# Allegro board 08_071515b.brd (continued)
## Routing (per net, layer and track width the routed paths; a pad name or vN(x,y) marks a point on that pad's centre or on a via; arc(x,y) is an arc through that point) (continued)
UNNAMED_14_ADLT8636_I23_TR: length 2.3
  TOP w0.254: VR1.18 17.78,12.64 17.21,12.07 C204.1
UNNAMED_14_ADLTC3307_I51_FB: length 3.6
  TOP w0.254: R108.2 C220.2 ; C220.2 U17.12 ; C220.2 R109.1
UNNAMED_14_ADLTC3307_I51_MODE: length 1.8
  TOP w0.14: v1(43.56,14.61) 43.63,14.67 U17.9
  BOTTOM w0.508: R5.2 42.97,14.61 v1(43.56,14.61)
UNNAMED_14_ADLTC3310_I15_FB: length 10.5
  TOP w0.254: U16.18 C208.2
  TOP w0.305: 33.66,13.58 33.66,11.66 34.14,11.17 R97.2 R107.1 C209.1 ; 33.66,13.58 34.54,13.58 R101.2 35.81,13.71 R102.1 ; 33.66,13.58 C208.2
UNNAMED_14_ADLTC3310_I15_ITH: length 9.5
  TOP w0.254: U16.17 32.38,14.28 31.68,13.58
  TOP w0.305: C193.1 C195.1 31.68,13.58 31.94,13.32 31.94,10.73 32.5,10.17 R97.1
UNNAMED_14_ADLTC3310_I15_PGOOD: length 2.2
  TOP w0.254: U16.14 30.73,15.64 30.1,15.64 29.46,14.99 R99.1
UNNAMED_14_ADLTC3310_I15_SSTT: length 3.9
  TOP w0.254: C202.1 29.08,13.65 29.72,14.29 31.44,14.29 31.88,14.73 U16.16
UNNAMED_14_CAP_I9_N2: length 2.8
  TOP w0.305: R91.1 30.87,10.61 31.11,10.86 C195.2
UNNAMED_14_RES_I39_N1: length 1.7
  TOP w0.305: R103.1 37.27,12.71 36.07,12.71 R102.2
UNNAMED_17_ADSP21835_I205_DMC0VREF1: length 27.5
  TOP w0.14: 41.25,56.54 41.02,56.54 U1.G20
  TOP w0.203: U1.J4 v1(27.42,54.94)
  TOP w0.305: v1(43.02,56.54) 41.25,56.54
  L7_SIG w0.127: 34.54,53.34 34.16,52.95 31.25,52.95 30.8,53.4 31.12,53.73 34.16,53.73 34.54,53.34
  L7_SIG w0.406: v1(27.42,54.94) 27.42,54.11 28.13,53.4 30.8,53.4 ; v1(43.02,56.54) 43.02,54.45 41.91,53.34 34.54,53.34
  BOTTOM w0.406: R2.2 v1(43.02,56.54)
UNNAMED_17_CAP_I61_N1: length 7.5
  TOP w0.14: U8.M8 v1(35.42,79.14)
  TOP w0.203: U8.H1 32.22,72.74
  TOP w0.406: 36.22,81.74 v1(36.22,80.74) ; 32.22,72.74 C32.1
  L4_SIG w0.406: v1(35.42,79.14) 35.03,79.14 34.75,79.43 34.75,80.43 35.05,80.74 v1(36.22,80.74)
UNNAMED_17_ICIS4XTR16256_I45_ZQ: length 3.3
  TOP w0.203: U8.L8 34.62,79.14 R4.1
UNNAMED_18_ICIS25XP512M_I1_SCK: length 4.6
  TOP w0.14: U4.B2 16.14,32.5 17.76,32.5 17.91,32.64 R49.2 R50.1
UNNAMED_18_ICIS25XP512M_I1_SO: length 4.9
  TOP w0.14: R51.2 R52.1 18.29,35.18 17.53,34.42 16.22,34.42 U4.D2
USB_DM: length 28.6
  TOP w0.133: D1.3 15.36,91.06 15.48,90.94 15.48,90.16 v1(15.18,89.86) 15.48,89.55 15.48,89.39 15.37,89.28 U15.5 ; P1.A7 30.24,91.02 30.33,90.93 30.33,90.11 v1(30.06,89.84)
  BOTTOM w0.133: v1(15.18,89.86) 15.48,89.55 15.48,89.1 15.76,88.82 17.17,88.82 18.84,90.49 30.18,90.49 30.36,90.31 30.36,90.14 v1(30.06,89.84) 30.36,89.54 30.36,89.25 30.64,88.96 31.6,88.96 31.88,89.25 31.88,90.97 31.6,91.25 30.74,91.25 30.61,91.39 30.61,91.58 30.88,91.85 P1.B7
USB_DP: length 27.8
  TOP w0.133: D1.4 15.87,91.06 15.74,90.93 15.74,90.16 v1(16.04,89.86) 15.74,89.55 15.74,89.42 15.87,89.28 U15.4 ; P1.A6 30.63,90.92 30.63,90.13 v1(30.92,89.84)
  BOTTOM w0.133: v1(16.04,89.86) 15.74,89.55 15.74,89.21 15.87,89.07 17.06,89.07 18.73,90.74 30.29,90.74 30.62,90.42 30.62,90.14 v1(30.92,89.84) 30.62,89.54 30.62,89.35 30.75,89.22 31.49,89.22 31.62,89.35 31.62,90.87 31.49,91 30.63,91 30.35,91.28 30.35,91.58 30.08,91.85 P1.B6
USB_TYPEC: length 12.3
  TOP w0.305: C158.1 29.23,89.77 P1.A9 29.23,92.22 P1.B4 ; P1.A4 31.73,92.22 P1.B9
  TOP w0.508: C158.1 D15.C ; v2(15.62,92.96) 15.62,92.96 D1.1
  L6_PWR w0.508: P1.B4 29.28,91.38 ; P1.B9 31.68,91.38
  BOTTOM w0.508: v2(8.06,92.49) E1.1 8,91.12 C183.1
  vias: v2(4.57,17.14) v2(4.57,16.38) v2(4.57,15.62) v2(5.46,17.14) v2(5.46,16.38) v2(5.46,15.62)
VTT: length 25
  TOP w0.254: U2.6 56.37,73.39
  TOP w0.267: U2.9 54.87,73.92 54.99,74.04
  BOTTOM w0.203: RN7.8 34.06,85.69 34.06,86.22 ; 33.56,86.54 RN7.7
  BOTTOM w0.254: 44.02,76.69 43.28,76.69 RN1.7 ; 44.02,76.69 44.02,76.19 43.42,76.19 RN1.8 ; 44.02,76.69 44.02,77.19 ; RN6.7 33.7,67.41 33.7,66.61 ; 36.27,86.34 36.27,85.69 RN4.5 ; 37.4,66.61 RN5.6 ; 44.02,80.89 43.37,80.89 RN3.5 ; RN5.5 37.9,67.27 37.9,66.61 ; RN6.5 34.7,67.27 34.7,66.61 ; 44.02,77.19 44.02,77.69 43.42,77.69 RN1.5 ; 44.02,77.19 43.28,77.19 RN1.6 ; 33.2,66.61 33.2,67.27 RN6.8 ; 36.4,66.61 36.4,67.27 RN5.8 ; RN4.8 37.77,85.69 37.77,86.34 ; 44.02,72.99 43.37,72.99 RN2.8 ; 34.2,66.61 RN6.6 ; RN3.8 43.37,79.39 44.02,79.39 ; 44.02,80.39 RN3.6 ; RN4.7 37.27,86.34 ; RN5.7 36.9,66.61 ; 44.02,73.99 RN2.6 ; RN4.6 36.77,86.34 ; RN2.5 43.37,74.49 44.02,74.49 ; 44.02,79.89 RN3.7 ; 44.02,73.49 RN2.7
  vias: v2(56.77,77.72) v2(56.77,76.96) v2(56.77,76.2) v2(56.77,75.44) v2(56.77,74.68) v2(56.77,73.91) v2(57.53,77.72) v2(57.53,76.96) v2(57.53,76.2) v2(57.53,75.44) v2(57.53,74.68) v2(57.53,73.91) v2(57.73,72.95) v2(57.73,72.18) v2(58.29,77.72) v2(58.29,76.96) v2(58.29,76.2) v2(58.29,75.44) v2(58.29,74.68) v2(58.29,73.91) v2(59.05,77.72) v2(59.05,76.96) v2(59.05,76.2) v2(59.05,75.44) v2(59.05,74.68) v2(59.05,73.91)
XSPI_CLK: length 19.1
  TOP w0.14: v1(27.81,38.99) 27.81,38.73 28.34,38.21 U27.2
  L5_SIG w0.127: v1(27.81,38.99) 28.68,38.13 28.68,36.2 29.07,35.8 30.82,35.8 31.75,34.87 39.32,34.87 v1(40.39,35.94)
  BOTTOM w0.14: R67.2 R110.1 v1(40.39,35.94)
XSPI_CS1*: length 16.8
  TOP w0.14: U27.5 28.2,36.71 v1(27.81,36.32)
  L5_SIG w0.127: v1(27.81,36.32) 28.74,35.39 30.76,35.39 31.66,34.49 34.87,34.49 35.41,33.96 38.94,33.96 39.78,34.8 v1(40.39,34.8)
  BOTTOM w0.14: R39.1 R68.1 v1(40.39,34.8)
XSPI_CS2*: length 12.8
  TOP w0.14: v1(32.89,35.43) 32.89,35.69 32.37,36.21 U27.9
  L5_SIG w0.127: v1(32.89,35.43) 33.35,35.89 33.35,37.01 34.01,37.67 34.82,37.67 35.69,38.53 40.11,38.53 v1(40.42,38.23)
  BOTTOM w0.14: R40.1 R69.1 v1(40.42,38.23)
XSPI_DQ0: length 34.8
  TOP w0.14: v1(21.46,38.99) 21.46,38.73 21.99,38.21 U22.2
  L8_SIG w0.127: v1(21.46,38.99) 22.73,40.26 29.72,40.26 30.63,39.34 32.1,39.34 32.39,39.62 35.46,39.62 36.09,38.99 38.19,38.99 38.64,38.53 39.8,38.53 40.01,38.73 41.15,38.73 42.16,37.72 42.16,36.83 42.52,36.47 50.61,36.47 v1(51.02,36.07)
  BOTTOM w0.14: R119.2 v1(51.02,36.07)
XSPI_DQ1: length 41.3
  TOP w0.14: U22.5 21.85,36.71 v1(21.46,36.32)
  L8_SIG w0.127: v1(51.02,30.35) 49.74,30.35 49.67,30.28 40.21,30.28 39.93,30.56 38.33,30.56 38.28,30.61 37.92,30.61 37.87,30.56 32.08,30.56 32.03,30.61 31.4,30.61 31.34,30.56 25.63,30.56 25.58,30.61 24.03,30.61 23.09,29.67 20.23,29.67 19.56,30.34 19.56,33.78 20.19,34.42 20.95,34.42 21.46,34.92 v1(21.46,36.32)
  BOTTOM w0.14: R118.2 v1(51.02,30.35)
XSPI_DQ2: length 39.1
  TOP w0.14: v1(26.54,35.43) 26.54,35.69 26.02,36.21 U22.9
  L8_SIG w0.127: v1(26.54,35.43) 26.97,35.86 29.79,35.86 30.73,34.92 38.86,34.92 40.77,33.02 40.77,31.11 41.28,30.61 49.53,30.61 49.91,30.99 51.82,30.99 52.32,31.5 52.32,37.05 v1(51.02,38.35)
  BOTTOM w0.14: R117.2 v1(51.02,38.35)
XSPI_DQ3: length 28.1
  TOP w0.14: U22.11 v1(26.54,37.21)
  L8_SIG w0.127: v1(26.54,37.21) 27,37.67 28.27,37.67 29.13,38.53 37.67,38.53 38.56,37.64 40.84,37.64 42.34,36.14 49.8,36.14 v1(51.02,34.92)
  BOTTOM w0.14: R116.2 v1(51.02,34.92)
XSPI_DQ4: length 22.6
  TOP w0.14: U29.2 34.69,38.21 34.16,38.73 v1(34.16,38.99)
  L5_SIG w0.127: v1(34.16,38.99) 38.4,38.99 38.91,39.5 40.54,39.5 41.78,38.25 48.54,38.25 50.19,36.6 50.19,34.61 v1(51.02,33.78)
  BOTTOM w0.14: R115.2 v1(51.02,33.78)
XSPI_DQ5: length 22.6
  TOP w0.14: U29.5 34.55,36.71 v1(34.16,36.32)
  L5_SIG w0.127: v1(51.02,32.64) 49.76,33.9 49.76,36.2 48.92,37.03 44.27,37.03 43.64,37.67 38.76,37.67 38.25,37.16 35,37.16 v1(34.16,36.32)
  BOTTOM w0.14: R114.2 v1(51.02,32.64)
XSPI_DQ6: length 18.1
  TOP w0.14: U29.9 38.72,36.21 39.24,35.69 v1(39.24,35.43)
  L8_SIG w0.127: v1(39.24,35.43) 40.77,35.43 41.28,34.92 41.28,31.11 41.4,30.99 49.15,30.99 49.66,31.5 v1(51.02,31.5)
  BOTTOM w0.14: R112.2 v1(51.02,31.5)
XSPI_DQ7: length 19.7
  TOP w0.14: U29.11 v1(39.24,37.21)
  L5_SIG w0.127: v1(51.02,29.21) 49.43,30.8 49.43,35.94 49,36.37 42.27,36.37 41.43,37.21 v1(39.24,37.21)
  BOTTOM w0.14: R111.2 v1(51.02,29.21)
XSPI_EN*: length 84.5
  TOP w0.14: v1(32.89,38.99) 32.89,38.73 32.37,38.21 U27.13 ; U29.4 v1(34.16,37.21) ; U22.13 26.02,38.21 26.54,38.73 v1(26.54,38.99) ; U29.13 38.72,38.21 39.24,38.73 v1(39.24,38.99) ; U24.13 v2(18.14,60.73) ; v1(39.24,36.32) 38.85,36.71 U29.10 ; U22.10 26.15,36.71 v1(26.54,36.32) ; U29.1 v1(35.95,39.74) ; U27.1 v1(29.6,39.74) ; U22.4 v1(21.46,37.21) ; v1(32.89,36.32) 32.5,36.71 U27.10 ; U22.1 v1(23.25,39.74) ; U27.4 v1(27.81,37.21)
  L4_SIG w0.127: v1(39.24,38.99) 39.67,38.56 39.67,36.75 v1(39.24,36.32) ; v1(32.89,36.32) 33.32,36.75 33.32,38.56 v1(32.89,38.99) ; v1(26.54,36.32) 26.97,36.75 26.97,38.56 v1(26.54,38.99)
  L7_SIG w0.127: v1(17.53,37.21) 15.62,39.12 15.62,41.53 16.64,42.55 16.64,44.58 17.14,45.09 17.14,57.79 18.14,58.78 v2(18.14,60.73)
  L8_SIG w0.127: v1(17.53,37.21) 17.87,37.55 21.12,37.55 v1(21.46,37.21) 25.65,37.21 v1(26.54,36.32) 26.92,36.32 v1(27.81,37.21) 32,37.21 v1(32.89,36.32) 33.27,36.32 v1(34.16,37.21) 35.39,35.98 38.9,35.98 v1(39.24,36.32) ; v1(39.24,38.99) 38.89,39.34 36.35,39.34 v1(35.95,39.74) ; v1(26.54,38.99) 24,38.99 v1(23.25,39.74) ; v1(29.6,39.74) 30.35,38.99 v1(32.89,38.99)
  BOTTOM w0.14: R36.1 R35.2 21.07,37.6 v1(21.46,37.21)
XSPI_INT*: length 2.6
  TOP w0.14: U25.A5 v1(47.72,37.59)
  BOTTOM w0.14: R122.1 47.72,38.46 v1(47.72,37.59)
XSPI_RSTO*: length 2.6
  TOP w0.14: U25.A2 v1(44.72,37.59)
  BOTTOM w0.14: v1(44.72,37.59) 44.72,38.47 R121.1
XSPI_RWDS: length 25
  TOP w0.14: U27.11 v1(32.89,37.21)
  L8_SIG w0.127: v1(51.02,37.21) 51.74,36.49 51.74,34.72 51.31,34.29 50.55,34.29 49.02,35.81 41.53,35.81 40.56,36.78 38.66,36.78 38.23,37.21 36.09,37.21 35.66,37.64 33.32,37.64 v1(32.89,37.21)
  BOTTOM w0.14: R120.2 v1(51.02,37.21)

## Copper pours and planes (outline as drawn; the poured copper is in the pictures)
DGND on TOP (solid shape): 62.04,71.88 59.84,71.88 59.84,78.1 62.04,78.1
DGND on TOP (solid shape): 62.04,66.93 59.84,66.93 59.84,71.5 62.04,71.5
DGND on TOP: 45.77,15.53 46.74,15.53 46.91,15.7 48.51,15.7 48.73,15.93 50.66,15.93 51.05,16.32 51.05,20.07 47.31,20.07 47.31,17.02 46.99,16.71 46.23,16.71 45.77,16.25
DGND on TOP: 30.43,12.87 27.6,12.87 27.3,12.57 27.3,8.83 27.62,8.51 38.35,8.51 38.8,8.95 38.8,14.41 36.94,16.28 33.32,16.28 33.32,16 34.17,16 35.62,14.54 36.45,14.54 36.83,14.16 36.83,13.83 38.23,13.83 38.35,13.7 38.35,9.59 37.85,9.08 29.72,9.08 29.15,9.65 29.15,11.05 29.39,11.3 30.47,11.3 30.47,12.83
DGND on TOP: 10.34,23.34 13.03,23.34 13.03,25.39 12.83,25.59 10.48,25.59 10.34,25.45
DGND on TOP: 18.16,15.63 16.25,15.63 15.51,16.37 15.51,16.55 10.16,16.55 10.15,16.54 10.15,13.67 10.41,13.4 13.21,13.4 13.4,13.59 13.4,14.61 13.74,14.95 15.51,14.95 15.91,15.35 18.16,15.35
DGND on TOP: 14.66,13.15 13.6,13.15 13.46,13.02 13.46,9.21 14.03,8.64 23.94,8.64 24.24,8.94 24.24,11.09 22.24,11.09 21.76,10.61 20.02,10.61 20.02,9.41 19.81,9.21 17.84,9.21 17.54,9.51 17.54,10.59 17.51,10.61 15.76,10.61 14.66,11.72
DGND on TOP: 45.77,14.31 45.77,13.22 45.85,13.14 46.93,13.14 47.12,12.95 47.12,12.07 46.93,11.88 46.05,11.88 46.05,11.04 46.36,10.73 47.94,10.73 49.19,11.98 49.19,13.48 49.02,13.65 46.42,13.65 46.21,13.86 46.21,14.31
DGND on TOP: 0.7,100.9 62.8,100.9 62.8,0.7 0.7,0.7 ; 39 cut-outs
DGND on TOP: 44.4,15.53 43.43,15.53 43.26,15.7 41.66,15.7 41.44,15.93 39.51,15.93 39.12,16.32 39.12,20.07 42.04,20.07 42.74,19.37 42.74,17.08 42.99,16.83 43.82,16.83 44.4,16.25
DGND on BOTTOM: 0.7,100.9 62.8,100.9 62.8,0.7 0.7,0.7 ; 24 cut-outs
DGND on BOTTOM: 37.63,23.19 37.63,16.28 39.24,14.67 46.61,14.67 47.18,15.24 47.18,17.11 47.17,17.12 42.13,17.12 41.91,17.34 41.91,22.63 41.35,23.19
DGND on L2_PWR: 50.8,100.9 62.8,100.9 62.8,65.15 57.15,65.15 57.15,74.04 57.08,74.22 56.9,74.3 50.8,74.3
DGND on L3_GND: 0.7,100.9 62.8,100.9 62.8,0.7 0.7,0.7
DGND on L3_GND: 28.28,9.89 28.29,9.88 28.31,9.87 35.61,9.87 35.63,9.87 35.94,9.99 36.26,9.87 36.27,9.87 38.05,9.87 38.07,9.88 38.07,9.89 38.07,16.46 38.07,16.48 38.05,16.48 37.67,16.48 37.66,16.48 37.65,16.47 37.21,16.17 36.77,16.47 36.76,16.48 36.75,16.48 36.28,16.48 36.26,16.48 36.25,16.47 35.81,16.17 35.38,16.47 35.37,16.48 35.35,16.48 35.26,16.48 35.25,16.48 35.24,16.47 34.8,16.17 34.36,16.46 34.34,16.47 34.32,16.45 34.32,14.92 34.34,14.9 34.36,14.91 35.27,14.73 34.36,14.55 34.34,14.57 34.32,14.54 34.32,13.65 34.31,13.63 34.29,13.63 28.31,13.63 28.29,13.62 28.28,13.6
DGND on L5_SIG: 62.8,100.9 62.8,0.7 0.7,0.7 0.7,100.9 ; 28 cut-outs
DGND on L6_PWR: 30.42,88.01 62.8,88.01 62.8,72.33 51.82,72.33 51.64,72.25 51.56,72.07 51.56,65.28 35.12,65.28 35.12,66.99 38.29,66.99 38.47,67.07 38.54,67.25 38.54,68.26 40.45,68.26 40.63,68.34 40.7,68.52 40.7,70.74 41.53,70.74 41.71,70.81 41.78,70.99 41.78,72.39 42.61,72.39 42.79,72.46 42.86,72.64 42.86,77.91 42.79,78.09 42.61,78.17 41.85,78.17 41.85,78.8 42.61,78.8 42.79,78.88 42.86,79.06 42.86,81.92 42.79,82.09 42.61,82.17 39.94,82.17 39.94,86.04 39.87,86.22 39.69,86.3 30.42,86.3
DGND on L7_SIG: 62.8,100.9 62.8,0.7 0.7,0.7 0.7,100.9 ; 5 cut-outs
DGND on L9_GND: 62.8,100.9 62.8,0.7 0.7,0.7 0.7,100.9
VDD_CONNECTOR on TOP (solid shape): 3.71,14.45 4.45,13.72 5.71,13.72 5.71,12.57 3.3,12.57 2.44,13.44 2.44,18.41 3.71,18.41
VDD_DMC on TOP: 40.07,23.81 40.07,21.08 40.7,20.45 42.16,20.45 43.37,19.24 46.94,19.24 46.94,21.07 46.8,21.21 44.39,21.21 43.82,21.78 43.82,22.1 41.91,24 40.26,24
VDD_DMC on TOP: 59.44,71.5 57.24,71.5 57.24,70.39 56.85,69.99 55.37,69.99 55.37,66.67 59.44,66.67
VDD_DMC on BOTTOM: 47.17,17.93 42.37,17.93 42.37,20.57 42.24,20.7 40.7,20.7 40.01,21.4 40.01,23.11 40.83,23.94 42.48,23.94 44.2,22.22 45.72,22.22 45.91,22.03 45.91,21.27 47.17,20.02
VDD_DMC on L6_PWR: outline of 98 points within 0.7,0.7 62.8,88.01
VDD_EXT on TOP (solid shape): 10.67,5.71 7.75,5.71 7.75,7.62 10.67,7.62
VDD_EXT on TOP (solid shape): 59.18,61.21 57.15,61.21 56.36,60.42 56.36,59.44 52.06,59.44 52.06,62.66 53.47,64.07 59.18,64.07
VDD_EXT on L5_SIG (solid shape): 10.67,5.71 7.75,5.71 7.75,7.62 10.67,7.62
VDD_EXT on TOP: 54.42,72.37 54.42,73.66 54.17,73.91 52.34,73.91 52.01,73.58 52.01,72.12 53.39,72.12 53.64,72.37
VDD_EXT on TOP: 21.68,20.12 21.68,26.96 20.95,27.69 15.24,27.69 14.4,26.85 14.4,23.99 18.8,23.99 20.1,22.68 20.1,20.12
VDD_EXT on TOP: 33.32,16.5 34.24,16.5 34.42,16.32 37.66,16.32 37.83,16.5 37.83,18.58 35.83,18.58 35.83,18.24 35.61,18.02 34.59,18.02 34.59,17.43 34.44,17.28 33.32,17.28
VDD_EXT on TOP: 39.84,15.32 39.18,14.66 39.18,9.72 39.75,9.14 50.42,9.14 51.24,9.97 51.24,14.29 50.22,15.32 45.78,15.32 45.77,15.31 45.77,15.03 46.56,15.03 46.89,14.7 47.57,14.7 48.26,14.02 49.16,14.02 49.61,13.57 49.61,11.83 48.01,10.22 43.88,10.22 43.55,10.55 43.55,11.88 42.41,11.88 42.23,12.07 42.23,13.72 42.54,14.03 44.4,14.03 44.4,15.31 44.39,15.32
VDD_EXT on TOP: 30.94,17.28 29.98,17.28 29.82,17.43 29.82,18.02 28.82,18.02 28.64,18.2 28.64,18.83 26.63,18.83 26.61,18.81 26.61,15.81 26.67,15.75 29.4,15.75 29.65,16 30.94,16
VDD_EXT on BOTTOM: 21.74,23.55 17.79,23.55 17.14,24.19 17.14,27.05 17.4,27.3 21.21,27.3 21.74,26.77
VDD_EXT on L2_PWR: 0.7,100.9 50.29,100.9 50.29,74.04 50.37,73.86 50.55,73.79 56.64,73.79 56.64,64.9 56.72,64.72 56.9,64.64 62.8,64.64 62.8,0.7 0.7,0.7 0.7,6.6 2.67,6.6 2.85,6.68 2.92,6.86 2.92,8.57 38.04,8.57 38.22,8.65 38.29,8.83 38.29,13.46 38.22,13.64 38.04,13.72 28.26,13.72 28.26,14.86 28.18,15.04 28,15.11 26.42,15.11 26.42,17.53 38.54,17.53 38.72,17.6 38.8,17.78 38.8,27.56 38.72,27.74 38.54,27.81 29.08,27.81 28.9,27.74 28.83,27.56 28.83,24.7 9.14,24.7 9.14,48.26 11.62,48.26 11.62,45.59 11.69,45.41 11.87,45.34 11.97,45.36 12.06,45.42 23.75,45.42 23.87,45.47 23.93,45.59 23.93,52.78 27.64,52.78 27.64,48.96 27.69,48.83 27.81,48.78 37.34,48.78 37.46,48.83 37.52,48.96 37.52,51.96 39.5,51.96 39.62,52.01 39.67,52.13 39.67,58.55 39.62,58.67 39.5,58.72 31.17,58.72 31.17,62.05 31.22,62.13 31.24,62.23 31.17,62.41 30.99,62.48 0.7,62.48 ; 1 cut-out
VDD_EXT on L5_SIG: outline of 98 points within 3.07,5.74 26.33,44.11
VDD_INPUT on TOP: 25.92,17.75 21.25,17.75 19.84,16.35 19.2,16.35 19.2,16.63 19.61,16.63 19.81,16.83 19.81,18.61 20.55,19.34 22.56,19.34 23.03,19.81 25.78,19.81 25.92,19.67
VDD_INPUT on TOP: 4.98,21.34 4.98,17.91 6.35,17.91 7.43,18.99 9.84,18.99 10.15,18.68 10.15,17.75 14.82,17.75 16.23,16.35 16.87,16.35 16.87,16.63 16.45,16.63 16.32,16.76 16.32,18.54 15.52,19.34 13.5,19.34 13.03,19.82 13.03,22.12 10.25,22.12 9.46,21.34
VDD_INPUT on BOTTOM: 9.91,21.21 13.08,21.21 14.22,20.07 25.65,20.07 25.65,17.53 9.91,17.53
VDD_INT on TOP: 28.04,28.78 28.04,22.29 36.22,22.29 36.22,28.78
VDD_INT on BOTTOM: 28.47,25.96 28.47,20.51 28.49,20.5 36.39,20.5 36.39,26.67 35.81,27.24 31.06,27.24 29.78,25.96
VDD_INT on L2_PWR: 0.7,61.98 30.81,61.98 30.81,58.55 30.86,58.42 30.99,58.37 39.32,58.37 39.32,52.31 37.34,52.31 37.21,52.26 37.16,52.13 37.16,49.14 27.99,49.14 27.99,52.96 27.94,53.08 27.81,53.14 23.75,53.14 23.62,53.08 23.57,52.96 23.57,45.77 12.13,45.77 12.13,48.51 12.05,48.69 11.87,48.77 8.89,48.77 8.71,48.69 8.64,48.51 8.64,24.45 8.71,24.27 8.89,24.19 29.08,24.19 29.26,24.27 29.34,24.45 29.34,27.3 38.29,27.3 38.29,18.03 26.16,18.03 25.98,17.96 25.91,17.78 25.91,14.86 25.98,14.68 26.16,14.61 27.75,14.61 27.75,13.46 27.82,13.28 28,13.21 37.78,13.21 37.78,9.08 2.67,9.08 2.49,9.01 2.41,8.83 2.41,7.11 0.7,7.11
VDD_REF on TOP (solid shape): 62.23,52.83 60.71,52.83 60.71,54.61 59.69,55.63 59.69,58.55 59.05,59.18 57.66,59.18 57.66,60.45 59.05,60.45 59.69,61.09 59.69,63.18 62.23,63.18
VDD_REF on L6_PWR: 47.1,60.13 62.8,60.13 62.8,49.4 56.13,49.4 55.95,49.33 55.88,49.15 55.88,33.72 53.09,33.72 52.91,33.64 52.83,33.46 52.83,27.94 52.91,27.76 53.09,27.69 56.32,27.69 56.32,21.53 48.77,21.53 48.77,26.61 48.69,26.79 48.51,26.86 44.7,26.86 44.7,42.55 44.63,42.72 44.45,42.8 33.27,42.8 33.18,42.78 33.09,42.72 27.93,42.72 27.93,52.21 32.7,52.21 32.83,52.26 32.88,52.39 32.88,55.96 35.32,55.96 35.32,52.39 35.37,52.26 35.5,52.21 41.92,52.21 42,52.15 42.1,52.13 42.28,52.21 42.35,52.39 42.35,55.39
DMC0_VREF on TOP (solid shape): 49.78,81.03 49.78,65.02 44.2,65.02 44.2,79.63 43.94,80.01 42.04,80.01 41.91,80.14 41.91,81.53 42.04,81.66 49.15,81.66
DMC0_VREF on BOTTOM (solid shape): 47.29,56.21 44.32,56.21 44.32,57.02 47.29,57.02
DMC0_VREF on L8_SIG (solid shape): 45.34,65.02 44.96,64.64 44.96,57.15 45.21,56.9 45.72,56.9 45.72,56.13 44.58,56.13 44.2,56.51 44.2,65.79 44.45,66.04 45.34,66.04
UNNAMED_13_CAP_I3_N1 on TOP, BOTTOM: 24.89,99.31 24.89,92.27 25.27,91.88 26.42,91.88 27.37,92.84 27.37,94.55 27.5,94.68 33.4,94.68 33.53,94.55 33.53,92.65 34.29,91.88 35.81,91.88 36.07,92.14 36.07,99.25 35.69,99.63 25.21,99.63
UNNAMED_14_ADLT8636_I23_SW1 on TOP: 14.4,20.19 16.13,20.19 16.76,19.56 16.76,17.91 17.14,17.53 17.14,16.84 18.41,16.84 18.41,17.91 17.91,18.41 17.91,19.81 18.29,20.19 18.8,20.19 18.8,21.84 14.4,21.84
UNNAMED_14_ADLTC3307_I51_SW1 on TOP: 44.7,15.61 44.7,16.65 44.13,17.21 43.37,17.21 43.23,17.35 43.23,18.48 46.94,18.48 46.94,17.35 46.8,17.21 46.04,17.21 45.47,16.64 45.47,16.63 45.47,15.61
UNNAMED_14_ADLTC3310_I15_SW1 on TOP: 31.24,17.79 31.24,18.99 30.3,19.93 30.28,19.93 30.28,20.89 33.99,20.89 33.99,19.93 33.02,18.96 33.02,17.79
UNNAMED_17_CAP_I42_N1 on TOP: 50.16,69.22 54.48,69.22 54.48,70.1 51.94,70.1 51.05,70.99 50.16,70.99
UNNAMED_17_CAP_I61_N1 on TOP (solid shape): 39.62,84.07 39.62,82.04 40.01,81.66 41.28,81.66 41.47,81.47 41.47,67.88 40.89,67.31 34.16,67.31 33.53,67.94 33.53,70.24 33.26,70.52 31.75,70.52 31.75,72.26 34.42,72.26 35.05,71.63 35.05,69.34 35.43,68.96 39.5,68.96 39.88,69.34 39.88,80.14 39.5,80.52 38.86,80.52 38.48,80.9 38.48,83.55 38.23,83.81 37.54,83.81 37.27,83.51 37.27,80.71 36.96,80.39 35.81,80.39 35.81,82.04 36.83,82.04 36.83,84.2 37.08,84.45 39.24,84.45
USB_TYPEC on TOP (solid shape): 8.79,14.86 4.09,14.86 4.09,17.53 6.63,17.53 7.52,18.41 8.79,18.41
USB_TYPEC on L6_PWR: 0.7,100.9 62.8,100.9 62.8,88.52 18.73,88.52 18.55,88.44 18.48,88.27 18.48,70.74 7.11,70.74 6.93,70.66 6.86,70.48 6.86,14.61 0.7,14.61
VTT on TOP: 59.44,80.01 52.71,80.01 52.71,78.49 54.86,78.49 54.86,74.3 54.74,74.17 54.74,72.37 55.01,72.37 55.01,73.05 55.05,73.09 57.15,73.09 57.24,73 57.24,71.69 59.44,71.69
VTT on BOTTOM: 32.66,67.34 38.42,67.34 38.42,68.52 38.48,68.58 40.13,68.58 40.39,68.83 40.39,70.74 40.64,70.99 43.43,70.99 43.69,71.25 45.07,71.25 45.07,72.64 43.63,72.64 43.63,74.8 45.07,74.8 45.07,75.82 43.69,75.82 43.69,77.98 45.07,77.98 45.07,78.99 43.63,78.99 43.63,81.15 45.07,81.15 45.07,82.99 42.99,82.99 42.29,83.69 42.29,84.77 41.76,85.31 39.92,85.31 39.33,85.89 38.58,85.89 38.52,85.95 33.44,85.95 33.44,88.26 51.44,88.26 51.82,87.88 51.82,80.14 52.11,79.84 59.56,79.84 59.56,71.88 56.9,71.88 56.9,72.58 55.44,74.04 52.07,74.04 51.69,73.66 51.69,66.55 51.44,66.29 43.75,66.29 43.3,65.84 40.75,65.84 40.58,66.1 32.66,66.1

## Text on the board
User.Comments: 5.    SEE CRYSTAL OSCILLATOR PIN 1 DETAILS: | 7.    SMOOTHEN EDGES AND FREE FROM BURRS AFTER DEPANELIZATION PROCESS. | 4.    SEE DETAIL A FOR D15. | 6.    SINGULATE BOARD AFTER ASSEMBLY PROCESS | A. SEE DETAIL B FOR CRYSTALS - Y1-Y6. | DETAIL A | DETAIL B
Ref Des/Assembly Top: A | C
Ref Des/Silkscreen Top: A | C | ADSP21835W-EV-SOM
XSECTION_CHART: FAB NOTES REVISION: 12TH OF SEPTEMBER 2022 | ROHS COMPLIANCE NOTE: | 8.   IMPEDANCE REQUIREMENTS: IF NO STACKUP IS DEFINED, THE VENDOR IS ALLOWED TO ADJUST THE DIELECTRIC | 13.  PLATING SPECIFICATION: | 9.   FILLET OPTIONS TO ENHANCE RELIABILITY AT PAD JUNCTIONS WHERE SPACING PERMITS. | 10.  THIEVING: | 11.  LAYER TO LAYER REGISTRATION SHALL BE WITHIN 0.003 INCHES. | 12.  DRILL SIZES ARE FINISHED HOLE SIZES. ALL HOLES SHALL BE LOCATED WITHIN 0.005 INCHES DTP,UNLESS SPECIFIED. | 14.  SURFACE FINISH: | 15.  SOLDERMASK: | 1.   DIMENSIONS ARE IN INCHES (EXCEPT WHERE NOTED). | ALL DOCUMENTS & SPECIFICATIONS REFERRED TO BELOW SHOULD BE THE LATEST REVISIONS. | 2.  BOARD MATERIAL: | 3.   ALL LAMINATES & BONDING MATERIALS SHOULD BE SELECTED FROM IPC-4101 OR IPC-4103,(TG>170 DEGC TD>300 DEGC) | 4.   REFER TO IPC-6010 SERIES, CLASS 2 FOR FABRICATION. | 5.   REFER TO LAMINATION DIAGRAM FOR OVERALL BOARD THICKNESS, TOLERANCE APPLIES AFTER ALL LAMINATION AND PLATING | 6.   BOW & TWIST NOT TO EXCEED 0.0075 INCHES (0.75%) PER LINEAR INCH AND SHOULD BE MEASURED PER IPC-TM-650, METHOD 2.4.22. | 7.   ACCEPTABILITY PER ADI SPECIFICATION TST00115. | 16.  APPLY SILKSCREEN TO BOTH SIDES USING A NON-CONDUCTIVE, EPOXY BASED INK PER ARTWORK. | HOMOGENOUS MATERIALS IN THIS BOARD SHALL BE COMPLIANT WITH | THE EU RoHS DIRECTIVE 2002/95/EC | ( ) FILLETS ALLOWED | (X) FILLETS NOT ALLOWED | ( ) VENDOR MAY ADD THIEVING TO COMPENSATE FOR LOW COPPER DENSITY AREAS MAINTAINING A MINIMUM | (X) VENDOR MAY NOT ADD THIEVING TO COMPENSATE FOR LOW COPPER DENSITY AREAS. | (X) LPI | ( ) WLCSP | ( ) LDI | COLOR | ( ) GREEN | (X) BLUE | ( ) RED | ( ) BLACK | (X) WHITE | ( ) YELLOW | HINDER PROPER SOLDER WICKING. BARREL RELIEF ON SOLDERMASK ALLOWED IN UNFILLED VIA IN PAD HOLES. | (X) REFER TO LAMINATION DIAGRAM FOR FINISHED COPPER WEIGHT/THICKNESS REQUIRMENTS | (X) IMMERSION GOLD (ENIG) 1.58-3.94 MICRO INCHES OVER 118-236 MICRO INCHES MIN. OF ELECTROLESS NICKEL PER IPC-4552 | ( ) OSP (ORGANIC SOLDERABILITY PRESERVATIVE) | ( ) IMMERSION SILVER | ( ) SOFT WIRE BONDABLE GOLD 30-50 MICRO INCHES OF SOFT WIRE | ( ) EDGE CONNECTOR FINGERS ARE TO BE PLATED WITH 100 MICRO-INCHES(.0001") OF LOW STRESS | THICKNESS & TRACE WIDTHS TO MEET THE IMPEDANCE REQUIREMENT. IF SPECIFIED, THE VENDOR MUST | TRACE WIDTH & SPACING THAT IMPACT THE REQUIREMENTS MUST HAVE WRITTEN APPROVAL FROM ADI. | MINIMUM BARREL PLATING OF 0.001 INCHES. PLATED HOLES SHALL NOT BE ROUGH OR IRREGULAR SO AS TO | SOLDERMASK OVER BARE COPPER OR BARE GOLD (BOTH SIDES) TO MEET IPC-SM-840. | IF PRESENT,DO NOT MODIFY SOLDERMASK DEFINED PADS (MASK OPENINGS LESS THAN COPPER PAD) WITHOUT APPROVAL. | MEET THE REQUIREMENTS LISTED IN THE IMPEDANCE TABLE. ANY ADJUSTMENT MADE TO THE DEFINED STACKUP, | PROCESSES. FINISHED THICKNESS MEASURED FROM TOP COPPER TO BOTTOM COPPER. | (X)  ISOLA 370HR OR EQUIVALENT | ( )  ISOLA-FR408HR OR EQUIVALENT | ( )  ISOLA IS410 | ( )  MEGTRON 6 | ( )  NELCO-4000-13 | ( )  ROGERS 4350B | ( ) ROGERS 3003 | ( ) ARLON 85N | ( ) EM370D | ( )  OTHER ________________________ | UL FLAMMABILITY RATING 94V-0. BOARD MATERIAL & CONSTRUCTION SHALL MEET THE REQUIREMENTS OF UL796/UL796F. | BONDABLE GOLD OVER 100-150 MICRO INCHES OF NICKEL | NICKEL UNDER 30 MICRO-INCHES (.0003') OF GOLD | 0.100 INCH CLEARANCE FROM ALL COPPER FEATURES, | THE STARTING COPPER WEIGHT/THICKNESS CAN VARY AS LONG AS THE FINISHED COPPER | WEIGHT/THICKNESS IS NOT LESS THAN THE SPECIFIED VALUE. | UNLESS OTHERWISE SPECIFIED | (USE CHECKED ITEMS) | WORKMANSHIP SHALL CONFORM TO IPC-A-600, CLASS 2. | 24.  MINIMUM DESIGN LINE WIDTH IS .003 INCH | MINIMUM DESIGN SPACING IS .00325 INCH | 21.  INTENTIONAL SHORTS: | 17.  FINAL ELECTRICAL TEST TO BE PERFORMED USING PROVIDED IPC-D-356A NETLIST OR ODB++ FORMAT FILE. | 22.  PEMNUTS: | 23.  MANUFACTURER TO ETCH/STAMP WITH PERMANENT NON-CONDUCTIVE INK IN AREA PROVIDED: | 18.  A TIME DOMAIN REFLECTOMETER REPORT (TDR) FOR EACH IMPEDANCE CONTROLLED LAYER & A CERTIFICATE | 19.  IF PRESENT, ALL BLIND/BURIED VIAS WITH AN ASPECT RATIO <1:1 TO BE PLATED SHUT WITH COPPER WHEN | 20.  FOR VIA FILL INFORMATION REFER TO DRILL CHART: | IS ACCEPTABLE, ALL OTHER INSTANCES MUST BE REPORTED. | IF AN INTENTIONAL SHORT REPORT IS SUPPLIED AND DOES NOT MATCH THE FAB DATA THEN | THE PCB SHALL HAVE A VERIFICATION STAMP. | (X)  NON-CONDUCTIVE EPOXY FILL ALL 0.008 AND 0.012 INCHES DRILLED VIAS | ( )  COPPER FILL ALL 0.XXXX INCHES DRILLED VIAS | ( ) PEMNUTS TO BE INSTALLED BY FABRICATOR | ( ) PEMNUTS NOT TO BE INSTALLED BY FABRICATOR | (X) NOT APPLICABLE | USED AS VIA-IN-PAD OR AS A STACKED VIA. BLIND/BURIED VIAS WITH AN ASPECT RATIO >1:1 TO BE FILLED | A. UL CODE-FLAMMABILITY RATING FOR THOSE APPROVED MATERIALS(IF APPLICABLE) | B. DATE CODE | C. LOT NUMBER | D. MANUFACTURER LOGO | CAN'T BE PERFORMED BECAUSE THE TRACE LENGTH IS TOO SHORT ON THE OUTER LAYERS AT THE PIN ESCAPES | ADI APPROVAL IS REQUIRED. | OF COMPLIANCE SHALL BE PROVIDED BY VENDOR AT TIME OF SHIPMENT. INSTANCES WHERE TDR TESTING | WITH NON-CONDUCTIVE EPOXY. | TOOLING: | FINISH: | NOTES: | MATERIAL: | L1 | L2 | L3 | L4 | L5 | L6 | L7 | L8 | L9 | L10 | TESTING: | MISCELLANEOUS: | DESIGN CROSS SECTION CHART | ___________________________ | TOTAL THICKNESS 62 MIL | 1-10 | 1-2
PAGE_OUTLINE: B | CHANGES AS PER ECR-113417 | 21MAR23 | D. HARRINGTON | CUSTOMER EVALUATION Z
DIMENSION: - | SEE DETAIL A | " " | V-SCORE | DETAIL A | (REF) | PRIMARY SIDE | SECONDARY SIDE | DIA MAX | SEE NOTE 20
User.11: A | C | (CHECK DATASHEET) | BOTTOM VIEW
User.15: NOTE: ALL IMPEDANCE TOLERANCE +/-10% | LAYER | L1 | L4 | L5 | L7 | L8 | L10 | SE = SINGLE ENDED, DP = DIFFERENTIAL PAIR | 50 OHMS SE | 90 OHMS DP | 100 OHMS DP | IMPEDANCE | REFERENCE | L2 | L3 | L6 | L9 | LINE WIDTH | 5.25 MILS | 5.5 MILS | 3.5 MILS | 5 MILS | 3 MILS | 4.75 MILS | 7.5 MILS | SPACE | N/A | 7 MILS | IMPEDANCE TABLE | B
User.24: 08-      -07 | L2 PWR
User.25: 08-      -08 | L3 GND
User.26: 08-      -09 | L4 SIG
User.27: 08-      -10 | L5 SIG
User.28: 08-      -11 | L6 PWR
User.29: 08-      -12 | L7 SIG
User.30: 08-      -13 | L8 SIG
User.31: 08-      -14 | L9 GND
User.32: 3 | BLIND VIAS L1-L2 | DIA MAX | SEE NOTE 16
User.45: FIGURE | SIZE | 8.0 | 12.0 | 16.0 | 29.0 | 63.0 | 35.0 | 125.0 | 48.0x24.0 | PLATED | NON-PLATED | DRILL CHART: TOP to BOTTOM | ALL UNITS ARE IN MILS | QTY | 967 | 490 | 14 | 10 | 4 | 6 | 8 | TOLERANCE/NOTES
